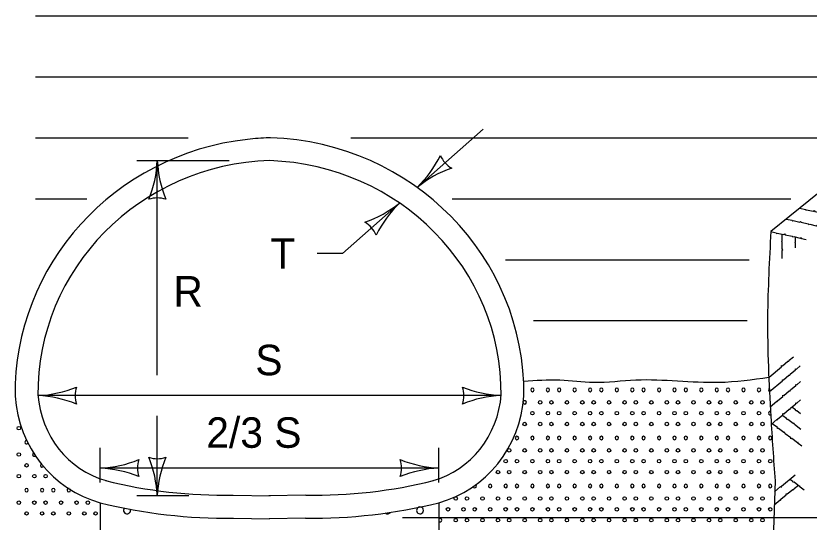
# Model space of a CAD drawing. Extents: x 49991.4 to 50021, y 49987.6 to 50011.4.
# Drawn here: x 50008.745 to 50010.306, y 49989.828 to 49990.824 of the extents above; entities that cross this region are included whole.
import ezdxf

# ---------------------------------------------------------------- set-up
doc = ezdxf.new("R2010")
doc.units = 0
for name, color, linetype in [('Level 1', 7, 'Continuous'), ('Level 2', 7, 'Continuous'), ('Level 3', 7, 'Continuous')]:
    doc.layers.add(name, color=color, linetype=linetype)

msp = doc.modelspace()

# ---------------------------------------------------------------- linework, layer by layer
at = {"layer": 'Level 1'}
for p, q in [((50008.7832, 49990.8245), (50010.7552, 49990.8245)), ((50008.7832, 49990.7045), (50010.5831, 49990.7045)), ((50008.7832, 49990.5845), (50009.0843, 49990.5845)), ((50009.2464, 49990.5845), (50009.2425, 49990.5845)), ((50009.404, 49990.5845), (50010.4213, 49990.5845)), ((50010.3536, 49990.4994), (50010.2312, 49990.3999)), ((50008.7832, 49990.4645), (50008.8848, 49990.4645)), ((50009.6035, 49990.4645), (50010.2706, 49990.4645)), ((50009.7087, 49990.3445), (50010.1882, 49990.3445)), ((50009.7637, 49990.2245), (50010.1846, 49990.2245)), ((50009.1724, 49989.8809), (50009.2454, 49989.8794)), ((50009.3159, 49989.8809), (50009.2427, 49989.8794)), ((50008.9108, 49989.8661), (50008.9108, 49989.7442)), ((50009.5775, 49989.866), (50009.5775, 49989.7409)), ((50009.1731, 49989.8359), (50009.2444, 49989.8344)), ((50009.3152, 49989.8359), (50009.2437, 49989.8344))]:
    msp.add_line(p, q, dxfattribs=at)
for points in [[(50010.2875, 49990.4457), (50010.2999, 49990.4435), (50010.3003, 49990.4418), (50010.3015, 49990.4428), (50010.3146, 49990.4399), (50010.3164, 49990.4413), (50010.3174, 49990.4395), (50010.3308, 49990.4367), (50010.3321, 49990.435), (50010.334, 49990.4358), (50010.3471, 49990.4328), (50010.3487, 49990.4339), (50010.3497, 49990.4321), (50010.3589, 49990.4303)], [(50010.2615, 49990.4246), (50010.2734, 49990.4221), (50010.2738, 49990.4204), (50010.275, 49990.4215), (50010.2882, 49990.4185), (50010.2898, 49990.4199), (50010.2909, 49990.4182), (50010.3044, 49990.4153), (50010.3056, 49990.4138), (50010.3076, 49990.4144), (50010.3205, 49990.4114), (50010.3222, 49990.4125), (50010.3232, 49990.4107), (50010.3323, 49990.4089)], [(50010.2311, 49990.4), (50010.2418, 49990.3977), (50010.2423, 49990.3959), (50010.2435, 49990.397), (50010.2567, 49990.3941), (50010.2583, 49990.3954), (50010.2594, 49990.3937), (50010.2728, 49990.3908), (50010.2741, 49990.3893), (50010.2761, 49990.3899), (50010.289, 49990.3869), (50010.2907, 49990.3881), (50010.2917, 49990.3863), (50010.3008, 49990.3844)], [(50010.2536, 49990.3469), (50010.2533, 49990.3626), (50010.2545, 49990.3641), (50010.2535, 49990.3657), (50010.2535, 49990.3793), (50010.252, 49990.3805), (50010.2536, 49990.3819), (50010.2531, 49990.395)], [(50010.2797, 49990.3676), (50010.2796, 49990.3772), (50010.2781, 49990.3785), (50010.2797, 49990.3799), (50010.2794, 49990.3894)], [(50010.2275, 49990.1133), (50010.2518, 49990.1338), (50010.2518, 49990.1359), (50010.2538, 49990.1357), (50010.2643, 49990.1446), (50010.2663, 49990.1447), (50010.2669, 49990.1466), (50010.2755, 49990.1536)], [(50010.2287, 49990.0849), (50010.2541, 49990.1062), (50010.254, 49990.1083), (50010.256, 49990.1081), (50010.2666, 49990.117), (50010.2686, 49990.1171), (50010.2692, 49990.119), (50010.2795, 49990.1275), (50010.2796, 49990.1295), (50010.2817, 49990.1291), (50010.2887, 49990.1353)], [(50010.23, 49990.0548), (50010.2428, 49990.066), (50010.2444, 49990.0652), (50010.2443, 49990.0668), (50010.2547, 49990.0754), (50010.2546, 49990.0776), (50010.2566, 49990.0774), (50010.2671, 49990.0863), (50010.2692, 49990.0863), (50010.2698, 49990.0882), (50010.2801, 49990.0967), (50010.2802, 49990.0987), (50010.2823, 49990.0984), (50010.2893, 49990.1045)], [(50010.2319, 49990.0203), (50010.2427, 49990.0299), (50010.2443, 49990.0291), (50010.2443, 49990.0307), (50010.2546, 49990.0393), (50010.2546, 49990.0415), (50010.2566, 49990.0413), (50010.2671, 49990.0502), (50010.2691, 49990.0502), (50010.2697, 49990.0521), (50010.2801, 49990.0606), (50010.2802, 49990.0626), (50010.2822, 49990.0623), (50010.2893, 49990.0684)], [(50010.2896, 49990.0412), (50010.282, 49990.0471), (50010.28, 49990.0467), (50010.2799, 49990.0488), (50010.2722, 49990.0543)], [(50010.29, 49990.0105), (50010.2775, 49990.0198), (50010.277, 49990.0218), (50010.275, 49990.0219), (50010.2644, 49990.0301), (50010.2624, 49990.0297), (50010.2622, 49990.0318), (50010.2548, 49990.0372)], [(50010.2919, 49989.9776), (50010.2846, 49989.9829), (50010.2849, 49989.9846), (50010.2834, 49989.9842), (50010.2727, 49989.9924), (50010.2706, 49989.9918), (50010.2703, 49989.9938), (50010.2593, 49990.002), (50010.2588, 49990.004), (50010.2568, 49990.0042), (50010.2462, 49990.0123), (50010.2442, 49990.012), (50010.2441, 49990.014), (50010.2317, 49990.023)], [(50010.2394, 49989.9091), (50010.2342, 49989.7543)], [(50010.2383, 49989.8874), (50010.2503, 49989.8977), (50010.2519, 49989.8969), (50010.2519, 49989.8985), (50010.2793, 49989.9207)], [(50010.2969, 49989.8906), (50010.2887, 49989.8966), (50010.2891, 49989.8983), (50010.2875, 49989.8979), (50010.2769, 49989.9063), (50010.2748, 49989.9057), (50010.2746, 49989.9078), (50010.2686, 49989.9121)], [(50010.2374, 49989.8619), (50010.2494, 49989.8721), (50010.251, 49989.8713), (50010.251, 49989.8729), (50010.2615, 49989.8814), (50010.2615, 49989.8835), (50010.2635, 49989.8833), (50010.2741, 49989.8921), (50010.2761, 49989.8921), (50010.2768, 49989.894), (50010.2855, 49989.9009)]]:
    msp.add_lwpolyline(points, dxfattribs=at)
for centre in [(50009.777, 49990.0637), (50009.7991, 49990.0637), (50009.8296, 49990.0637), (50009.8601, 49990.0637), (50009.8822, 49990.0637), (50009.9127, 49990.0637), (50009.9432, 49990.0637), (50009.9653, 49990.0637), (50009.9958, 49990.0637), (50010.0263, 49990.0637), (50010.0484, 49990.0637), (50010.0789, 49990.0637), (50010.1094, 49990.0637), (50010.1315, 49990.0637), (50010.162, 49990.0637), (50010.1925, 49990.0637), (50010.2146, 49990.0637), (50009.7617, 49990.0424), (50009.7617, 49990.0424), (50009.7922, 49990.0424), (50009.8144, 49990.0424), (50009.8448, 49990.0424), (50009.8448, 49990.0424), (50009.8753, 49990.0424), (50009.8975, 49990.0424), (50009.9279, 49990.0424), (50009.9279, 49990.0424), (50009.9584, 49990.0424), (50009.9806, 49990.0424), (50010.0111, 49990.0424), (50010.0111, 49990.0424), (50010.0415, 49990.0424), (50010.0637, 49990.0424), (50010.0942, 49990.0424), (50010.0942, 49990.0424), (50010.1246, 49990.0424), (50010.1468, 49990.0424), (50010.1773, 49990.0424), (50010.1773, 49990.0424), (50010.2077, 49990.0424), (50009.7465, 49990.021), (50009.777, 49990.021), (50009.7991, 49990.021), (50009.8296, 49990.021), (50009.8601, 49990.021), (50009.8822, 49990.021), (50009.9127, 49990.021), (50009.9432, 49990.021), (50009.9653, 49990.021), (50009.9958, 49990.021), (50010.0263, 49990.021), (50010.0484, 49990.021), (50010.0789, 49990.021), (50010.1094, 49990.021), (50010.1315, 49990.021), (50010.162, 49990.021), (50010.1925, 49990.021), (50010.2146, 49990.021), (50008.7507, 49990.0129), (50009.716, 49989.9691), (50009.7465, 49989.9691), (50009.777, 49989.9691), (50009.7991, 49989.9691), (50009.8296, 49989.9691), (50009.8601, 49989.9691), (50009.8822, 49989.9691), (50009.9127, 49989.9691), (50009.9432, 49989.9691), (50009.9653, 49989.9691), (50009.9958, 49989.9691), (50010.0263, 49989.9691), (50010.0484, 49989.9691), (50010.0789, 49989.9691), (50010.1094, 49989.9691), (50010.1315, 49989.9691), (50010.162, 49989.9691), (50010.1925, 49989.9691), (50010.2146, 49989.9691), (50008.7507, 49989.9609), (50008.7659, 49989.9396), (50008.7659, 49989.9396), (50009.7091, 49989.9478), (50009.7313, 49989.9478), (50009.7617, 49989.9478), (50009.7617, 49989.9478), (50009.7922, 49989.9478), (50009.8144, 49989.9478), (50009.8448, 49989.9478), (50009.8448, 49989.9478), (50009.8753, 49989.9478), (50009.8975, 49989.9478), (50009.9279, 49989.9478), (50009.9279, 49989.9478), (50009.9584, 49989.9478), (50009.9806, 49989.9478), (50010.0111, 49989.9478), (50010.0111, 49989.9478), (50010.0415, 49989.9478), (50010.0637, 49989.9478), (50010.0942, 49989.9478), (50010.0942, 49989.9478), (50010.1246, 49989.9478), (50010.1468, 49989.9478), (50010.1773, 49989.9478), (50010.1773, 49989.9478), (50010.2077, 49989.9478), (50010.2299, 49989.9478), (50009.6939, 49989.9264), (50009.716, 49989.9264), (50009.7465, 49989.9264), (50009.777, 49989.9264), (50009.7991, 49989.9264), (50009.8296, 49989.9264), (50009.8601, 49989.9264), (50009.8822, 49989.9264), (50009.9127, 49989.9264), (50009.9432, 49989.9264), (50009.9653, 49989.9264), (50009.9958, 49989.9264), (50010.0263, 49989.9264), (50010.0484, 49989.9264), (50010.0789, 49989.9264), (50010.1094, 49989.9264), (50010.1315, 49989.9264), (50010.162, 49989.9264), (50010.1925, 49989.9264), (50010.2146, 49989.9264), (50008.7507, 49989.9183), (50008.7812, 49989.9183), (50008.8033, 49989.9183), (50009.6108, 49989.8745), (50009.6329, 49989.8745), (50009.6634, 49989.8745), (50009.6939, 49989.8745), (50009.716, 49989.8745), (50009.7465, 49989.8745), (50009.777, 49989.8745), (50009.7991, 49989.8745), (50009.8296, 49989.8745), (50009.8601, 49989.8745), (50009.8822, 49989.8745), (50009.9127, 49989.8745), (50009.9432, 49989.8745), (50009.9653, 49989.8745), (50009.9958, 49989.8745), (50010.0263, 49989.8745), (50010.0484, 49989.8745), (50010.0789, 49989.8745), (50010.1094, 49989.8745), (50010.1315, 49989.8745), (50010.162, 49989.8745), (50010.1925, 49989.8745), (50010.2146, 49989.8745), (50008.7507, 49989.8663), (50008.7812, 49989.8663), (50008.8033, 49989.8663), (50008.8338, 49989.8663), (50008.8643, 49989.8663), (50008.8864, 49989.8663), (50008.7659, 49989.845), (50008.7659, 49989.845), (50008.7964, 49989.845), (50008.8186, 49989.845), (50008.849, 49989.845), (50008.849, 49989.845), (50008.8795, 49989.845), (50008.9017, 49989.845), (50009.5955, 49989.8532), (50009.5955, 49989.8532), (50009.626, 49989.8532), (50009.6482, 49989.8532), (50009.6786, 49989.8532), (50009.6786, 49989.8532), (50009.7091, 49989.8532), (50009.7313, 49989.8532), (50009.7617, 49989.8532), (50009.7617, 49989.8532), (50009.7922, 49989.8532), (50009.8144, 49989.8532), (50009.8448, 49989.8532), (50009.8448, 49989.8532), (50009.8753, 49989.8532), (50009.8975, 49989.8532), (50009.9279, 49989.8532), (50009.9279, 49989.8532), (50009.9584, 49989.8532), (50009.9806, 49989.8532), (50010.0111, 49989.8532), (50010.0111, 49989.8532), (50010.0415, 49989.8532), (50010.0637, 49989.8532), (50010.0942, 49989.8532), (50010.0942, 49989.8532), (50010.1246, 49989.8532), (50010.1468, 49989.8532), (50010.1773, 49989.8532), (50010.1773, 49989.8532), (50010.2077, 49989.8532), (50010.2299, 49989.8532), (50009.6108, 49989.8318), (50009.6329, 49989.8318), (50009.6634, 49989.8318), (50009.6939, 49989.8318), (50009.716, 49989.8318), (50009.7465, 49989.8318), (50009.777, 49989.8318), (50009.7991, 49989.8318), (50009.8296, 49989.8318), (50009.8601, 49989.8318), (50009.8822, 49989.8318), (50009.9127, 49989.8318), (50009.9432, 49989.8318), (50009.9653, 49989.8318), (50009.9958, 49989.8318), (50010.0263, 49989.8318), (50010.0484, 49989.8318), (50010.0789, 49989.8318), (50010.1094, 49989.8318), (50010.1315, 49989.8318), (50010.162, 49989.8318), (50010.1925, 49989.8318), (50010.2146, 49989.8318)]:
    msp.add_circle(centre, 0.00341, dxfattribs=at)
for centre, radius, start, end in [((50009.7617, 49990.0882), 0.00341, 0, 180), ((50009.7617, 49990.0881), 0.00341, 180, 0), ((50009.7617, 49990.0881), 0.00341, 180, 0), ((50009.7922, 49990.0882), 0.00341, 0, 180), ((50009.7922, 49990.0881), 0.00341, 180, 0), ((50009.8144, 49990.0882), 0.00341, 0, 180), ((50009.8144, 49990.0881), 0.00341, 180, 0), ((50009.8448, 49990.0882), 0.00341, 0, 180), ((50009.8448, 49990.0881), 0.00341, 180, 0), ((50009.8448, 49990.0881), 0.00341, 180, 0), ((50009.8753, 49990.0882), 0.00341, 0, 180), ((50009.8753, 49990.0881), 0.00341, 180, 0), ((50009.8975, 49990.0882), 0.00341, 0, 180), ((50009.8975, 49990.0881), 0.00341, 180, 0), ((50009.9279, 49990.0882), 0.00341, 0, 180), ((50009.9279, 49990.0881), 0.00341, 180, 0), ((50009.9279, 49990.0881), 0.00341, 180, 0), ((50009.9584, 49990.0882), 0.00341, 0, 180), ((50009.9584, 49990.0881), 0.00341, 180, 0), ((50009.9806, 49990.0882), 0.00341, 0, 180), ((50009.9806, 49990.0881), 0.00341, 180, 0), ((50010.0111, 49990.0882), 0.00341, 0, 180), ((50010.0111, 49990.0881), 0.00341, 180, 0), ((50010.0111, 49990.0881), 0.00341, 180, 0), ((50010.0415, 49990.0882), 0.00341, 0, 180), ((50010.0415, 49990.0881), 0.00341, 180, 0), ((50010.0637, 49990.0882), 0.00341, 0, 180), ((50010.0637, 49990.0881), 0.00341, 180, 0), ((50010.0942, 49990.0882), 0.00341, 0, 180), ((50010.0942, 49990.0881), 0.00341, 180, 0), ((50010.0942, 49990.0881), 0.00341, 180, 0), ((50010.1246, 49990.0882), 0.00341, 0, 180), ((50010.1246, 49990.0881), 0.00341, 180, 0), ((50010.1468, 49990.0882), 0.00341, 0, 180), ((50010.1468, 49990.0881), 0.00341, 180, 0), ((50010.1773, 49990.0882), 0.00341, 0, 180), ((50010.1773, 49990.0881), 0.00341, 180, 0), ((50010.1773, 49990.0881), 0.00341, 180, 0), ((50010.2077, 49990.0882), 0.00341, 0, 180), ((50010.2077, 49990.0881), 0.00341, 180, 0), ((50010.2299, 49990.0882), 0.00341, 113.2144, 180), ((50010.2299, 49990.0881), 0.00341, 180, 251.5244), ((50009.7465, 49990.0637), 0.00341, 188.7543, 153.6141), ((50010.2299, 49990.0424), 0.00341, 79.6084, 285.5712), ((50008.7659, 49989.9854), 0.00341, 81.2217, 180), ((50009.7313, 49989.9936), 0.00341, 0, 180), ((50009.7313, 49989.9935), 0.00341, 180, 0), ((50009.7617, 49989.9936), 0.00341, 0, 180), ((50009.7617, 49989.9935), 0.00341, 180, 0), ((50009.7617, 49989.9935), 0.00341, 180, 0), ((50009.7922, 49989.9936), 0.00341, 0, 180), ((50009.7922, 49989.9935), 0.00341, 180, 0), ((50009.8144, 49989.9936), 0.00341, 0, 180), ((50009.8144, 49989.9935), 0.00341, 180, 0), ((50009.8448, 49989.9936), 0.00341, 0, 180), ((50009.8448, 49989.9935), 0.00341, 180, 0), ((50009.8448, 49989.9935), 0.00341, 180, 0), ((50009.8753, 49989.9936), 0.00341, 0, 180), ((50009.8753, 49989.9935), 0.00341, 180, 0), ((50009.8975, 49989.9936), 0.00341, 0, 180), ((50009.8975, 49989.9935), 0.00341, 180, 0), ((50009.9279, 49989.9936), 0.00341, 0, 180), ((50009.9279, 49989.9935), 0.00341, 180, 0), ((50009.9279, 49989.9935), 0.00341, 180, 0), ((50009.9584, 49989.9936), 0.00341, 0, 180), ((50009.9584, 49989.9935), 0.00341, 180, 0), ((50009.9806, 49989.9936), 0.00341, 0, 180), ((50009.9806, 49989.9935), 0.00341, 180, 0), ((50010.0111, 49989.9936), 0.00341, 0, 180), ((50010.0111, 49989.9935), 0.00341, 180, 0), ((50010.0111, 49989.9935), 0.00341, 180, 0), ((50010.0415, 49989.9936), 0.00341, 0, 180), ((50010.0415, 49989.9935), 0.00341, 180, 0), ((50010.0637, 49989.9936), 0.00341, 0, 180), ((50010.0637, 49989.9935), 0.00341, 180, 0), ((50010.0942, 49989.9936), 0.00341, 0, 180), ((50010.0942, 49989.9935), 0.00341, 180, 0), ((50010.0942, 49989.9935), 0.00341, 180, 0), ((50010.1246, 49989.9936), 0.00341, 0, 180), ((50010.1246, 49989.9935), 0.00341, 180, 0), ((50010.1468, 49989.9936), 0.00341, 0, 180), ((50010.1468, 49989.9935), 0.00341, 180, 0), ((50010.1773, 49989.9936), 0.00341, 0, 180), ((50010.1773, 49989.9935), 0.00341, 180, 0), ((50010.1773, 49989.9935), 0.00341, 180, 0), ((50010.2077, 49989.9936), 0.00341, 0, 180), ((50010.2077, 49989.9935), 0.00341, 180, 0), ((50010.2299, 49989.9936), 0.00341, 0, 180), ((50010.2299, 49989.9935), 0.00341, 180, 0), ((50008.7659, 49989.9853), 0.00341, 180, 332.7773), ((50008.7659, 49989.9853), 0.00341, 180, 332.7773), ((50008.7812, 49989.9609), 0.00341, 99.5682, 322.205), ((50008.7964, 49989.9396), 0.00341, 99.3991, 341.3819), ((50008.7659, 49989.8908), 0.00341, 0, 180), ((50008.7964, 49989.8908), 0.00341, 0, 180), ((50008.8186, 49989.8908), 0.00341, 0, 180), ((50008.849, 49989.8908), 0.00341, 80.6454, 180), ((50009.6482, 49989.8989), 0.00341, 186.4263, 0), ((50009.6482, 49989.899), 0.00341, 0, 59.4232), ((50009.6786, 49989.899), 0.00341, 0, 180), ((50009.6786, 49989.8989), 0.00341, 180, 0), ((50009.6786, 49989.8989), 0.00341, 180, 0), ((50009.7091, 49989.899), 0.00341, 0, 180), ((50009.7091, 49989.8989), 0.00341, 180, 0), ((50009.7313, 49989.899), 0.00341, 0, 180), ((50009.7313, 49989.8989), 0.00341, 180, 0), ((50009.7617, 49989.899), 0.00341, 0, 180), ((50009.7617, 49989.8989), 0.00341, 180, 0), ((50009.7617, 49989.8989), 0.00341, 180, 0), ((50009.7922, 49989.899), 0.00341, 0, 180), ((50009.7922, 49989.8989), 0.00341, 180, 0), ((50009.8144, 49989.899), 0.00341, 0, 180), ((50009.8144, 49989.8989), 0.00341, 180, 0), ((50009.8448, 49989.899), 0.00341, 0, 180), ((50009.8448, 49989.8989), 0.00341, 180, 0), ((50009.8448, 49989.8989), 0.00341, 180, 0), ((50009.8753, 49989.899), 0.00341, 0, 180), ((50009.8753, 49989.8989), 0.00341, 180, 0), ((50009.8975, 49989.899), 0.00341, 0, 180), ((50009.8975, 49989.8989), 0.00341, 180, 0), ((50009.9279, 49989.899), 0.00341, 0, 180), ((50009.9279, 49989.8989), 0.00341, 180, 0), ((50009.9279, 49989.8989), 0.00341, 180, 0), ((50009.9584, 49989.899), 0.00341, 0, 180), ((50009.9584, 49989.8989), 0.00341, 180, 0), ((50009.9806, 49989.899), 0.00341, 0, 180), ((50009.9806, 49989.8989), 0.00341, 180, 0), ((50010.0111, 49989.899), 0.00341, 0, 180), ((50010.0111, 49989.8989), 0.00341, 180, 0), ((50010.0111, 49989.8989), 0.00341, 180, 0), ((50010.0415, 49989.899), 0.00341, 0, 180), ((50010.0415, 49989.8989), 0.00341, 180, 0), ((50010.0637, 49989.899), 0.00341, 0, 180), ((50010.0637, 49989.8989), 0.00341, 180, 0), ((50010.0942, 49989.899), 0.00341, 0, 180), ((50010.0942, 49989.8989), 0.00341, 180, 0), ((50010.0942, 49989.8989), 0.00341, 180, 0), ((50010.1246, 49989.899), 0.00341, 0, 180), ((50010.1246, 49989.8989), 0.00341, 180, 0), ((50010.1468, 49989.899), 0.00341, 0, 180), ((50010.1468, 49989.8989), 0.00341, 180, 0), ((50010.1773, 49989.899), 0.00341, 0, 180), ((50010.1773, 49989.8989), 0.00341, 180, 0), ((50010.1773, 49989.8989), 0.00341, 180, 0), ((50010.2077, 49989.899), 0.00341, 0, 180), ((50010.2077, 49989.8989), 0.00341, 180, 0), ((50010.2299, 49989.899), 0.00341, 0, 180), ((50010.2299, 49989.8989), 0.00341, 180, 0), ((50008.7659, 49989.8907), 0.00341, 180, 0), ((50008.7659, 49989.8907), 0.00341, 180, 0), ((50008.7964, 49989.8907), 0.00341, 180, 0), ((50008.8186, 49989.8907), 0.00341, 180, 0), ((50008.849, 49989.8907), 0.00341, 180, 0), ((50008.849, 49989.8907), 0.00341, 180, 0), ((50008.849, 49989.8908), 0.00341, 0, 38.9859), ((50008.9635, 49989.851), 0.00682, 140.4971, 282.921), ((50008.9636, 49989.851), 0.00682, 282.921, 20.8774), ((50009.4764, 49989.851), 0.00682, 282.921, 329.7915), ((50009.5404, 49989.851), 0.00682, 77.079, 282.921), ((50009.5405, 49989.851), 0.00682, 282.921, 77.079), ((50009.4763, 49989.851), 0.00682, 226.0209, 282.921), ((50009.5803, 49989.8318), 0.00341, 214.2022, 145.7978)]:
    msp.add_arc(centre, radius, start, end, dxfattribs=at)
for centre, major_axis, ratio, start_param, end_param in [((50009.2586, 49990.0814), (-0.5152, -0.0149), 0.976362, 4.796646, 6.264407), ((50009.2586, 49990.0814), (-0.5152, -0.0149), 0.976362, 4.715363, 4.796646), ((50009.2297, 49990.0814), (0.5152, -0.0149), 0.976362, 0.018778, 1.566912), ((50009.2586, 49990.0814), (-0.4703, -0.0136), 0.9741, 4.713552, 6.264407), ((50009.2297, 49990.0814), (0.4703, -0.0136), 0.9741, 0.018778, 1.566912), ((50008.9679, 49990.0939), (0, -0.2355), 0.956933, 4.789023, 6.027407), ((50008.9679, 49990.0939), (0, -0.1905), 0.946758, 4.789023, 6.027407), ((50009.5204, 49990.0939), (0, -0.1905), 0.946758, 0.255726, 1.494162), ((50009.5204, 49990.0939), (0, -0.2355), 0.956933, 0.255726, 1.494162), ((50009.1571, 49990.9519), (0, -1.0711), 0.955124, 6.050475, 6.2982), ((50009.3312, 49990.9519), (0, -1.0711), 0.955124, 6.26817, 6.515885), ((50009.1571, 49990.9519), (0, -1.1161), 0.956933, 6.050475, 6.2982), ((50009.3312, 49990.9519), (0, -1.1161), 0.956933, 6.26817, 6.515885)]:
    msp.add_ellipse(centre, major_axis=major_axis, ratio=ratio, start_param=start_param, end_param=end_param, dxfattribs=at)
for points in [[(50010.2312, 49990.3999), (50010.2247, 49990.2322), (50010.231, 49990.0355), (50010.2394, 49989.9091)], [(50010.2273, 49990.1123), (50010.1292, 49990.1026), (50009.9655, 49990.1073), (50009.8823, 49990.1026), (50009.8158, 49990.1073), (50009.7446, 49990.1045)]]:
    msp.add_spline(points, degree=3, dxfattribs=at)
at = {"layer": 'Level 3'}
for p, q in [((50009.5347, 49990.4867), (50009.6646, 49990.6016)), ((50009.1647, 49990.5394), (50008.9832, 49990.5394)), ((50009.0231, 49990.117), (50009.0233, 49990.5394)), ((50009.388, 49990.3568), (50009.5001, 49990.456)), ((50009.388, 49990.3568), (50009.3382, 49990.3568)), ((50009.7451, 49990.0759), (50009.7451, 49990.0855)), ((50009.7001, 49990.077), (50008.7882, 49990.077)), ((50009.0233, 49989.8794), (50009.0233, 49990.037)), ((50008.9108, 49989.9059), (50008.9108, 49989.9742)), ((50009.5775, 49989.9058), (50009.5775, 49989.9742)), ((50009.5775, 49989.9342), (50008.9108, 49989.9342)), ((50009.0853, 49989.8794), (50008.9832, 49989.8794)), ((50010.4332, 49989.8361), (50009.5057, 49989.8361))]:
    msp.add_line(p, q, dxfattribs=at)
for centre, radius, start, end in [((50009.3719, 49990.6534), 0.233, 314.328, 333.5778), ((50009.6307, 49990.5717), 0.0548, 203.6395, 239.3618), ((50008.8011, 49990.5486), 0.2223, 337.456, 357.6395), ((50009.256, 49990.5509), 0.233, 182.8273, 202.0772), ((50009.6751, 49990.3143), 0.2223, 108.9567, 129.1402), ((50009.0233, 49990.4112), 0.0548, 72.1388, 107.8612), ((50009.3597, 49990.6285), 0.2223, 288.9567, 309.1402), ((50009.6629, 49990.2894), 0.233, 134.328, 153.5778), ((50009.404, 49990.3711), 0.0548, 23.6395, 59.3618), ((50008.779, 49990.2992), 0.2223, 272.3605, 292.544), ((50008.9164, 49990.077), 0.0548, 162.1388, 197.8612), ((50009.5718, 49990.077), 0.0548, 342.1388, 17.8612), ((50009.7116, 49990.3098), 0.233, 247.9228, 267.1727), ((50008.7767, 49989.8443), 0.233, 67.9228, 87.1727), ((50009.7092, 49989.8549), 0.2223, 92.3605, 112.544), ((50009.0233, 49990.0076), 0.0548, 252.1388, 287.8612), ((50008.7906, 49989.8679), 0.233, 2.8273, 22.0772), ((50009.2454, 49989.8703), 0.2223, 157.456, 177.6395), ((50008.9017, 49990.1564), 0.2223, 272.3605, 292.544), ((50009.0391, 49989.9342), 0.0548, 162.1388, 197.8612), ((50009.4493, 49989.9342), 0.0548, 342.1388, 17.8612), ((50009.589, 49990.1669), 0.233, 247.9228, 267.1727), ((50008.8993, 49989.7015), 0.233, 67.9228, 87.1727), ((50009.5867, 49989.7121), 0.2223, 92.3605, 112.544)]:
    msp.add_arc(centre, radius, start, end, dxfattribs=at)

# ---------------------------------------------------------------- texts
at = {"layer": 'Level 2'}
for s, p in [('T', (50009.2461, 49990.3268)), ('R', (50009.0549, 49990.2523)), ('S', (50009.2162, 49990.117)), ('2/3 S', (50009.1197, 49989.9742))]:
    msp.add_text(s, height=0.06, dxfattribs=at).set_placement(p)

doc.saveas('drawing.dxf')
